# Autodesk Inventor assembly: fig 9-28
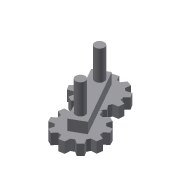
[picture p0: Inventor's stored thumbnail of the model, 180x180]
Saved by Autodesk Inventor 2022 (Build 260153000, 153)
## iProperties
Created: 2017-05
Part Number: fig 9-28
Document SubType Name: Assembly
Designer: CADCIM 00
Author: CADCIM 00
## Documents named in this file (3)
- D:\PROJECTS_2021\Resources\Part Files\c09_Inv_2022_prt\fig 9-28.iam
- D:\PROJECTS_2021\Resources\Part Files\c09_Inv_2022_prt\1.ipt
- D:\PROJECTS_2021\Resources\Part Files\c09_Inv_2022_prt\2.ipt
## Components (3 placed, 2 different names)
1. 1:1 — Flush:1, Rotation:1, Insert:2
2. 1:2 — Flush:1, Rotation:1, Insert:1
3. 2:1 — Insert:1, Insert:2
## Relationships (4: Insert 2, Flush 1, RelateRotation 1)
- Flush:1: 1:1 ↔ 1:2
- Rotation:1 [RelateRotation]: 1:1 ↔ 1:2
- Insert:1: 1:2 ↔ 2:1
- Insert:2: 1:1 ↔ 2:1
